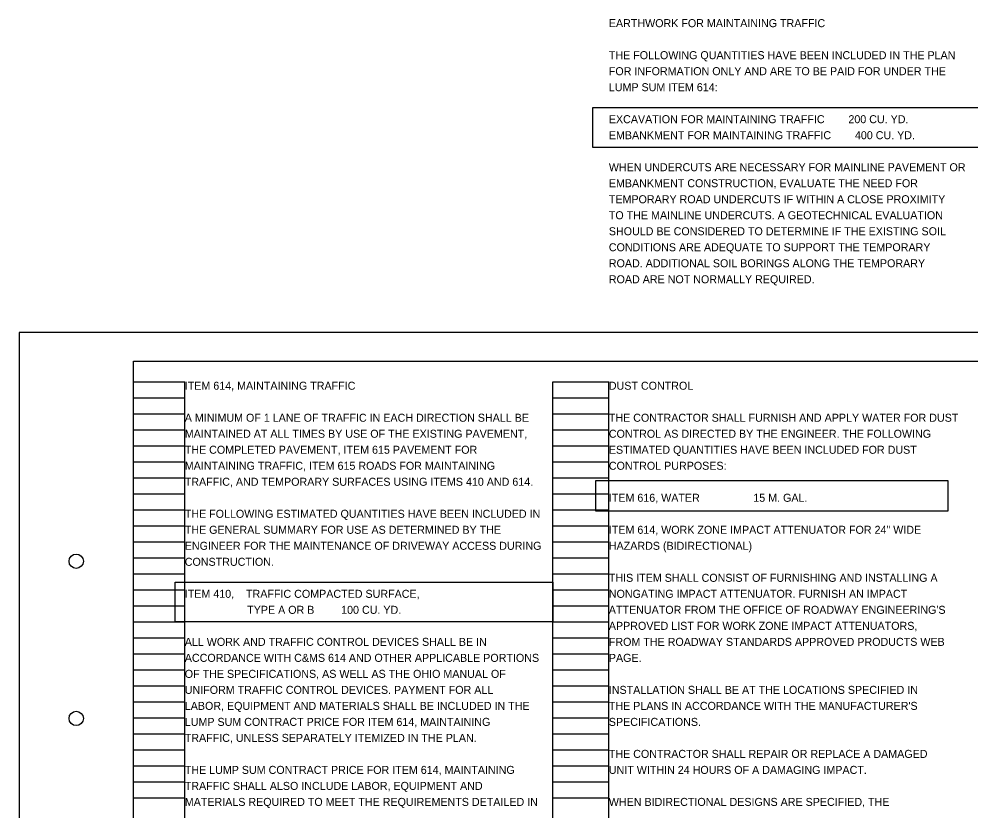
# Model space of a CAD drawing. Extents: x 0 to 34, y 0 to 27.5.
# Drawn here: x 0 to 16.66, y 13.63 to 27.48 of the extents above; entities that cross this region are included whole.
import ezdxf

# ---------------------------------------------------------------- set-up
doc = ezdxf.new("R2010")
doc.units = 0
for name, color, linetype in [('SC_Scratch1', 7, 'Continuous'), ('SH_Border', 7, 'Continuous'), ('SH_Cut_Line', 7, 'Continuous'), ('SH_Text', 7, 'Continuous')]:
    doc.layers.add(name, color=color, linetype=linetype)

msp = doc.modelspace()

# ---------------------------------------------------------------- linework, layer by layer
at = {"layer": 'SC_Scratch1'}
for p, q in [((2, 0.98), (2, 21.14)), ((2, 21.14), (2.9, 21.14)), ((2.9, 0.98), (2.9, 21.14)), ((9.34, 0.98), (9.34, 21.14)), ((9.34, 21.14), (10.32, 21.14)), ((10.32, 0.98), (10.32, 21.14)), ((2, 20.86), (2.9, 20.86)), ((9.34, 20.86), (10.32, 20.86)), ((2, 20.58), (2.9, 20.58)), ((9.34, 20.58), (10.32, 20.58)), ((2, 20.3), (2.9, 20.3)), ((9.34, 20.3), (10.32, 20.3)), ((2, 20.02), (2.9, 20.02)), ((9.34, 20.02), (10.32, 20.02)), ((2, 19.74), (2.9, 19.74)), ((9.34, 19.74), (10.32, 19.74)), ((2, 19.46), (2.9, 19.46)), ((9.34, 19.46), (10.32, 19.46)), ((2, 19.18), (2.9, 19.18)), ((9.34, 19.18), (10.32, 19.18)), ((2, 18.9), (2.9, 18.9)), ((9.34, 18.9), (10.32, 18.9)), ((2, 18.62), (2.9, 18.62)), ((9.34, 18.62), (10.32, 18.62)), ((2, 18.34), (2.9, 18.34)), ((9.34, 18.34), (10.32, 18.34)), ((2, 18.06), (2.9, 18.06)), ((9.34, 18.06), (10.32, 18.06)), ((2, 17.78), (2.9, 17.78)), ((9.34, 17.78), (10.32, 17.78)), ((2, 17.5), (2.9, 17.5)), ((9.34, 17.5), (10.32, 17.5)), ((2, 17.22), (2.9, 17.22)), ((9.34, 17.22), (10.32, 17.22)), ((2, 16.94), (2.9, 16.94)), ((9.34, 16.94), (10.32, 16.94)), ((2, 16.66), (2.9, 16.66)), ((9.34, 16.66), (10.32, 16.66)), ((2, 16.38), (2.9, 16.38)), ((9.34, 16.38), (10.32, 16.38)), ((2, 16.1), (2.9, 16.1)), ((9.34, 16.1), (10.32, 16.1)), ((2, 15.82), (2.9, 15.82)), ((9.34, 15.82), (10.32, 15.82)), ((2, 15.54), (2.9, 15.54)), ((9.34, 15.54), (10.32, 15.54)), ((2, 15.26), (2.9, 15.26)), ((9.34, 15.26), (10.32, 15.26)), ((2, 14.98), (2.9, 14.98)), ((9.34, 14.98), (10.32, 14.98)), ((2, 14.7), (2.9, 14.7)), ((9.34, 14.7), (10.32, 14.7)), ((2, 14.42), (2.9, 14.42)), ((9.34, 14.42), (10.32, 14.42)), ((2, 14.14), (2.9, 14.14)), ((9.34, 14.14), (10.32, 14.14)), ((2, 13.86), (2.9, 13.86)), ((9.34, 13.86), (10.32, 13.86))]:
    msp.add_line(p, q, dxfattribs=at)
for points in [[(10.041, 25.936), (16.938, 25.936), (16.938, 25.24), (10.041, 25.24)], [(10.09, 19.41), (16.254, 19.41), (16.254, 18.876), (10.09, 18.876)], [(2.73, 17.633), (9.34, 17.633), (9.34, 16.94), (2.73, 16.94)]]:
    msp.add_lwpolyline(points, close=True, dxfattribs=at)
at = {"layer": 'SH_Border'}
msp.add_lwpolyline([(2, 21.5), (33.5, 21.5), (33.5, 0.5), (2, 0.5)], close=True, dxfattribs=at)
for centre in [(1, 18), (1, 15.25)]:
    msp.add_circle(centre, 0.125, dxfattribs=at)
at = {"layer": 'SH_Cut_Line'}
msp.add_lwpolyline([(0, 0), (34, 0), (34, 22), (0, 22)], close=True, dxfattribs=at)

# ---------------------------------------------------------------- texts
at = {"layer": 'SH_Text'}
for s, p in [('EARTHWORK FOR MAINTAINING TRAFFIC', (10.32, 27.342)), ('THE FOLLOWING QUANTITIES HAVE BEEN INCLUDED IN THE PLAN ', (10.32, 26.782)), ('FOR INFORMATION ONLY AND ARE TO BE PAID FOR UNDER THE', (10.32, 26.502)), ('LUMP SUM ITEM 614:', (10.32, 26.222)), ('EXCAVATION FOR MAINTAINING TRAFFIC        200 CU. YD.', (10.32, 25.662)), ('EMBANKMENT FOR MAINTAINING TRAFFIC        400 CU. YD.', (10.32, 25.382)), ('WHEN UNDERCUTS ARE NECESSARY FOR MAINLINE PAVEMENT OR ', (10.32, 24.822)), ('EMBANKMENT CONSTRUCTION, EVALUATE THE NEED FOR ', (10.32, 24.542)), ('TEMPORARY ROAD UNDERCUTS IF WITHIN A CLOSE PROXIMITY ', (10.32, 24.262)), ('TO THE MAINLINE UNDERCUTS. A GEOTECHNICAL EVALUATION ', (10.32, 23.982)), ('SHOULD BE CONSIDERED TO DETERMINE IF THE EXISTING SOIL ', (10.32, 23.702)), ('CONDITIONS ARE ADEQUATE TO SUPPORT THE TEMPORARY ', (10.32, 23.422)), ('ROAD. ADDITIONAL SOIL BORINGS ALONG THE TEMPORARY ', (10.32, 23.142)), ('ROAD ARE NOT NORMALLY REQUIRED.', (10.32, 22.862)), ('ITEM 614, MAINTAINING TRAFFIC', (2.9, 21)), ('DUST CONTROL', (10.32, 21)), ('A MINIMUM OF 1 LANE OF TRAFFIC IN EACH DIRECTION SHALL BE ', (2.9, 20.44)), ('THE CONTRACTOR SHALL FURNISH AND APPLY WATER FOR DUST ', (10.32, 20.44)), ('MAINTAINED AT ALL TIMES BY USE OF THE EXISTING PAVEMENT, ', (2.9, 20.16)), ('CONTROL AS DIRECTED BY THE ENGINEER. THE FOLLOWING ', (10.32, 20.16)), ('THE COMPLETED PAVEMENT, ITEM 615 PAVEMENT FOR ', (2.9, 19.88)), ('ESTIMATED QUANTITIES HAVE BEEN INCLUDED FOR DUST ', (10.32, 19.88)), ('MAINTAINING TRAFFIC, ITEM 615 ROADS FOR MAINTAINING ', (2.9, 19.6)), ('CONTROL PURPOSES:', (10.32, 19.6)), ('TRAFFIC, AND TEMPORARY SURFACES USING ITEMS 410 AND 614. ', (2.9, 19.32)), ('ITEM 616, WATER                  15 M. GAL.', (10.32, 19.04)), ('THE FOLLOWING ESTIMATED QUANTITIES HAVE BEEN INCLUDED IN ', (2.9, 18.76)), ('THE GENERAL SUMMARY FOR USE AS DETERMINED BY THE ', (2.9, 18.48)), ('ITEM 614, WORK ZONE IMPACT ATTENUATOR FOR 24" WIDE', (10.32, 18.48)), ('ENGINEER FOR THE MAINTENANCE OF DRIVEWAY ACCESS DURING ', (2.9, 18.2)), ('HAZARDS (BIDIRECTIONAL)', (10.32, 18.2)), ('CONSTRUCTION.', (2.9, 17.92)), ('THIS ITEM SHALL CONSIST OF FURNISHING AND INSTALLING A ', (10.32, 17.64)), ('ITEM 410,    TRAFFIC COMPACTED SURFACE,', (2.9, 17.36)), ('NONGATING IMPACT ATTENUATOR. FURNISH AN IMPACT ', (10.32, 17.36)), ('                     TYPE A OR B         100 CU. YD.', (2.9, 17.08)), ("ATTENUATOR FROM THE OFFICE OF ROADWAY ENGINEERING'S ", (10.32, 17.08)), ('APPROVED LIST FOR WORK ZONE IMPACT ATTENUATORS, ', (10.32, 16.8)), ('ALL WORK AND TRAFFIC CONTROL DEVICES SHALL BE IN ', (2.9, 16.52)), ('FROM THE ROADWAY STANDARDS APPROVED PRODUCTS WEB ', (10.32, 16.52)), ('ACCORDANCE WITH C&MS 614 AND OTHER APPLICABLE PORTIONS ', (2.9, 16.24)), ('PAGE.', (10.32, 16.24)), ('OF THE SPECIFICATIONS, AS WELL AS THE OHIO MANUAL OF ', (2.9, 15.96)), ('UNIFORM TRAFFIC CONTROL DEVICES. PAYMENT FOR ALL ', (2.9, 15.68)), ('INSTALLATION SHALL BE AT THE LOCATIONS SPECIFIED IN ', (10.32, 15.68)), ('LABOR, EQUIPMENT AND MATERIALS SHALL BE INCLUDED IN THE ', (2.9, 15.4)), ("THE PLANS IN ACCORDANCE WITH THE MANUFACTURER'S ", (10.32, 15.4)), ('LUMP SUM CONTRACT PRICE FOR ITEM 614, MAINTAINING ', (2.9, 15.12)), ('SPECIFICATIONS.', (10.32, 15.12)), ('TRAFFIC, UNLESS SEPARATELY ITEMIZED IN THE PLAN.', (2.9, 14.84)), ('THE CONTRACTOR SHALL REPAIR OR REPLACE A DAMAGED ', (10.32, 14.56)), ('THE LUMP SUM CONTRACT PRICE FOR ITEM 614, MAINTAINING ', (2.9, 14.28)), ('UNIT WITHIN 24 HOURS OF A DAMAGING IMPACT.', (10.32, 14.28)), ('TRAFFIC SHALL ALSO INCLUDE LABOR, EQUIPMENT AND ', (2.9, 14)), ('MATERIALS REQUIRED TO MEET THE REQUIREMENTS DETAILED IN ', (2.9, 13.72)), ('WHEN BIDIRECTIONAL DESIGNS ARE SPECIFIED, THE ', (10.32, 13.72))]:
    msp.add_text(s, height=0.14, dxfattribs=at).set_placement(p)

doc.saveas('drawing.dxf')
